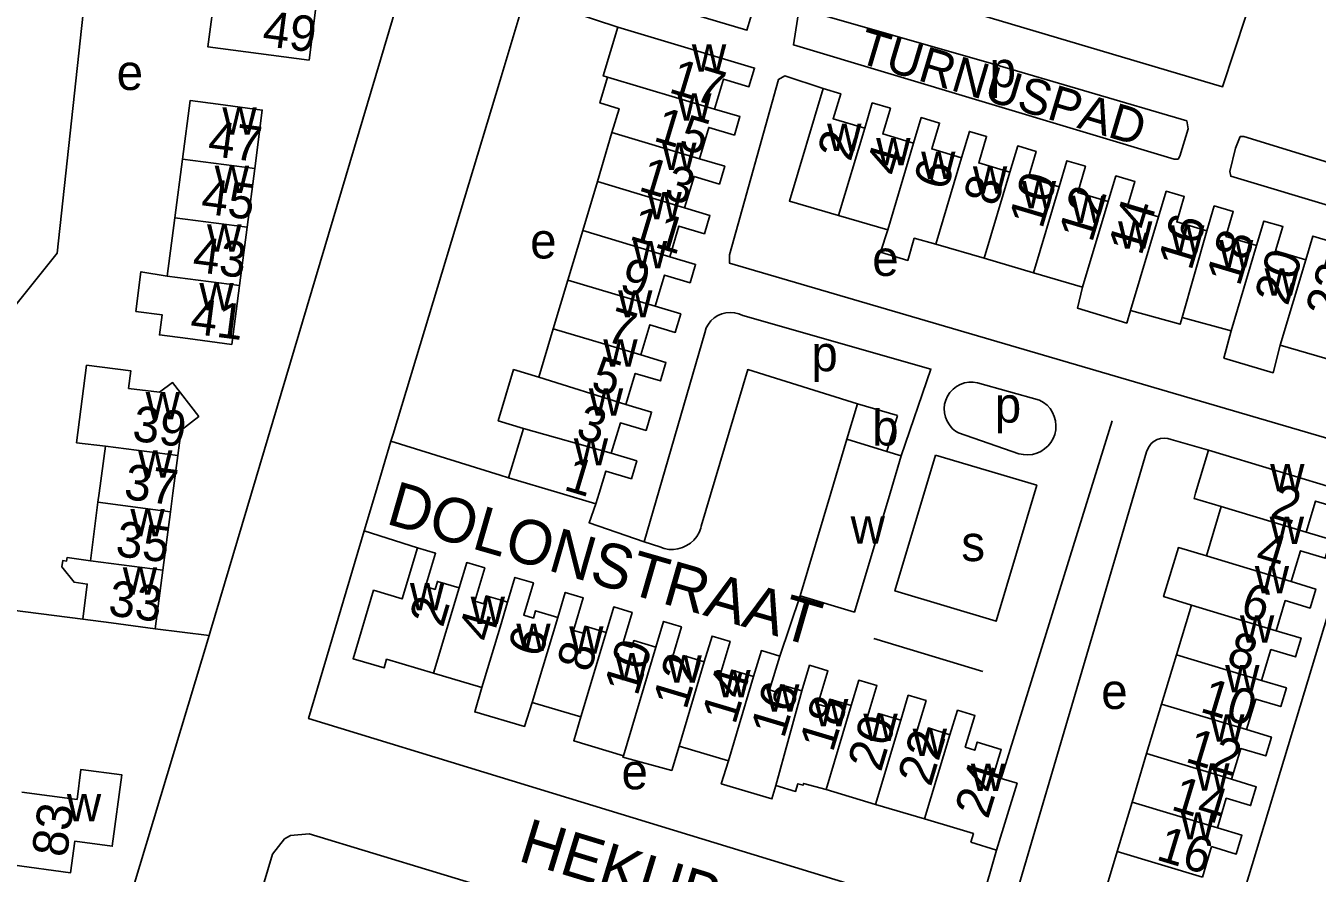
# Model space of a CAD drawing. Extents: x 161773 to 163836, y 384796 to 386521.
# Drawn here: x 162546.6 to 162692, y 386123.9 to 386219.3 of the extents above; entities that cross this region are included whole.
import ezdxf

# ---------------------------------------------------------------- set-up
doc = ezdxf.new("R2010")
doc.units = 0
for name, color, linetype in [('BLT_Basislijn', 7, 'Continuous'), ('BLT_Bebouwing', 7, 'Continuous'), ('BLT_Centroide', 7, 'Continuous'), ('BLT_Huisnummer', 7, 'Continuous'), ('BLT_Huisnummer_ tussenligend', 7, 'Continuous'), ('BLT_Onderverdeling_panden', 7, 'Continuous'), ('BLT_Straatnaam', 7, 'Continuous'), ('BLT_Straatnaam_verkleind', 7, 'Continuous')]:
    doc.layers.add(name, color=color, linetype=linetype)

msp = doc.modelspace()

# ---------------------------------------------------------------- linework, layer by layer
at = {"layer": 'BLT_Basislijn'}
for p, q in [((162613.25, 386219.12), (162602.84, 386222.55)), ((162623.03, 386184.72), (162616.23, 386161.19)), ((162653.73, 386179.08), (162660.73, 386177.13)), ((162668.89, 386174.8), (162656.4, 386134.57)), ((162658.4, 386171.11), (162651.6, 386173.44)), ((162675.53, 386172.72), (162679.74, 386171.49)), ((162672.77, 386171.3), (162656.86, 386117.36)), ((162590.71, 386160.52), (162584.72, 386162.44)), ((162616.23, 386161.19), (162617.98, 386160.61)), ((162531.15, 386155.33), (162553.03, 386152.48)), ((162633.77, 386155.11), (162631.48, 386148.33)), ((162561.18, 386151.41), (162567.26, 386150.66)), ((162654.32, 386146.61), (162642.07, 386150.31)), ((162655.88, 386126.5), (162653.53, 386118.37))]:
    msp.add_line(p, q, dxfattribs=at)
for points in [[(162567.26, 386150.66), (162567.41, 386151.18), (162572.02, 386166.67), (162600, 386260.71), (162602, 386267.43)], [(162540.64, 386154.24), (162544.92, 386187.1), (162550.17, 386193.67), (162555.68, 386244.61)], [(162606.67, 386234.6), (162681.32, 386212.4), (162683.95, 386220.36)], [(162603.89, 386225.89), (162627.79, 386218.76), (162629.02, 386222.85), (162605.25, 386230.19)], [(162602.84, 386222.55), (162600, 386213.16), (162587.96, 386173.29), (162587.72, 386172.5)], [(162655.32, 386215.01), (162633.68, 386221.2), (162633.02, 386217.11), (162675.87, 386204.25), (162676.31, 386204.27), (162676.5, 386204.6), (162677.44, 386207.67), (162677.29, 386208.56), (162655.32, 386215.01)], [(162636.36, 386212.21), (162632.07, 386213.62), (162631.35, 386213.24), (162625.82, 386193.5), (162625.83, 386192.55), (162698.69, 386171.22)], [(162708.24, 386199.25), (162683.7, 386206.8), (162683.3, 386206.8), (162682.79, 386205.5), (162682.15, 386202.86), (162682.23, 386202.34), (162706.87, 386194.97)], [(162627.31, 386186.66), (162626.86, 386186.85), (162626.39, 386186.97), (162625.91, 386187.01), (162625.43, 386186.97), (162624.95, 386186.85), (162624.51, 386186.66), (162624.1, 386186.39), (162623.74, 386186.07), (162623.45, 386185.68), (162623.21, 386185.26), (162623.03, 386184.72)], [(162627.31, 386186.66), (162648.49, 386180.63), (162645.14, 386170.87)], [(162622.64, 386162.94), (162627.87, 386180.58), (162640.23, 386176.73)], [(162653.73, 386179.08), (162653.24, 386179.15), (162652.75, 386179.15), (162652.27, 386179.07), (162651.8, 386178.9), (162651.37, 386178.67), (162650.98, 386178.37), (162650.64, 386178.01), (162650.37, 386177.6), (162650.17, 386177.15), (162650.04, 386176.68), (162649.99, 386176.18), (162650.02, 386175.69), (162650.12, 386175.21), (162650.31, 386174.76), (162650.57, 386174.34), (162650.89, 386173.96), (162651.27, 386173.65), (162651.6, 386173.44)], [(162660.73, 386177.13), (162661.17, 386176.88), (162661.56, 386176.56), (162661.9, 386176.18), (162662.18, 386175.75), (162662.38, 386175.29), (162662.52, 386174.8), (162662.57, 386174.29), (162662.54, 386173.78), (162662.43, 386173.28), (162662.25, 386172.81), (162661.99, 386172.37), (162661.67, 386171.98), (162661.29, 386171.64), (162660.87, 386171.36), (162660.4, 386171.15), (162659.91, 386171.02), (162659.4, 386170.97), (162658.9, 386171), (162658.4, 386171.11)], [(162587.72, 386172.5), (162585.98, 386166.67), (162584.72, 386162.44)], [(162600.96, 386168.4), (162600, 386168.7), (162587.72, 386172.5)], [(162675.53, 386172.72), (162675.14, 386172.83), (162674.74, 386172.87), (162674.34, 386172.82), (162673.96, 386172.7), (162673.6, 386172.51), (162673.29, 386172.24), (162673.04, 386171.93), (162672.86, 386171.57), (162672.77, 386171.3)], [(162649.02, 386170.96), (162644.44, 386155.67), (162655.83, 386152.26), (162660.4, 386167.56), (162649.02, 386170.96)], [(162610.78, 386165.46), (162610.02, 386163.33), (162616.23, 386161.19)], [(162697.19, 386166.25), (162681.58, 386114.67), (162679.99, 386111.76), (162677.03, 386111.25), (162656.86, 386117.36)], [(162584.72, 386162.44), (162578.45, 386141.3), (162600, 386134.72), (162649.94, 386119.45), (162650.62, 386119.25)], [(162617.98, 386160.61), (162618.47, 386160.44), (162618.99, 386160.34), (162619.51, 386160.33), (162620.02, 386160.39), (162620.52, 386160.54), (162620.99, 386160.76), (162621.43, 386161.04), (162621.81, 386161.39), (162622.14, 386161.8), (162622.4, 386162.25), (162622.59, 386162.74), (162622.64, 386162.94)], [(162517.27, 386157.06), (162513.65, 386127.2), (162515.18, 386125.55), (162517.05, 386125.1), (162553.21, 386120.54), (162557.19, 386120.68), (162558.62, 386122.04), (162567.26, 386150.66)], [(162600.83, 386121.55), (162600, 386121.81), (162578.52, 386128.33), (162576.4, 386128.15), (162575.75, 386127.77), (162574.38, 386126.02), (162560.06, 386077.9), (162560.16, 386075.81), (162561.56, 386074.11), (162571.68, 386071.14)]]:
    msp.add_lwpolyline(points, dxfattribs=at)
at = {"layer": 'BLT_Bebouwing'}
for p, q in [((162610.95, 386201.73), (162612.6, 386207.26)), ((162564.25, 386204.25), (162563.39, 386197.66)), ((162571.53, 386196.61), (162572.39, 386203.2)), ((162609.3, 386196.22), (162610.95, 386201.73)), ((162563.39, 386197.66), (162562.53, 386191.07)), ((162643.63, 386196.29), (162638.11, 386197.91)), ((162570.67, 386190.02), (162571.53, 386196.61)), ((162607.63, 386190.65), (162609.3, 386196.22)), ((162654.49, 386193.1), (162649.05, 386194.7)), ((162660.03, 386191.48), (162654.49, 386193.1)), ((162665.57, 386189.85), (162660.03, 386191.48)), ((162605.98, 386185.17), (162607.63, 386190.65)), ((162682.27, 386184.95), (162676.76, 386186.42)), ((162604.36, 386179.73), (162605.98, 386185.17)), ((162640.23, 386176.73), (162639.04, 386172.73)), ((162644.73, 386175.39), (162640.23, 386176.73)), ((162643.52, 386171.36), (162644.73, 386175.39)), ((162600.96, 386168.4), (162602.63, 386173.96)), ((162645.14, 386170.87), (162643.52, 386171.36)), ((162695.13, 386166.85), (162679.74, 386171.49)), ((162554.75, 386165.64), (162553.89, 386159.06)), ((162681.16, 386165.16), (162679.49, 386159.6)), ((162562.04, 386157.99), (162562.9, 386164.57)), ((162561.18, 386151.41), (162562.04, 386157.99)), ((162676.14, 386148.48), (162677.82, 386154.07)), ((162676.14, 386148.48), (162674.46, 386142.93)), ((162597.96, 386144.79), (162592.52, 386146.41)), ((162609.08, 386141.49), (162603.62, 386143.11)), ((162674.46, 386142.93), (162672.77, 386137.35)), ((162625.7, 386136.56), (162620.16, 386138.2)), ((162672.77, 386137.35), (162671.13, 386131.9)), ((162642.26, 386131.64), (162636.69, 386133.3)), ((162647.77, 386130), (162642.26, 386131.64)), ((162671.13, 386131.9), (162669.45, 386126.34)), ((162655.88, 386126.5), (162652.97, 386127.39)), ((162669.45, 386126.34), (162667.79, 386120.83))]:
    msp.add_line(p, q, dxfattribs=at)
for points in [[(162579.35, 386221.92), (162578.5, 386215.4), (162567.12, 386216.88), (162567.97, 386223.4), (162568.71, 386223.3)], [(162612.11, 386213.5), (162611.61, 386213.63), (162613.25, 386219.12)], [(162613.25, 386219.12), (162628.64, 386214.51), (162628.01, 386212.41), (162625.16, 386213.27), (162624.15, 386209.89)], [(162612.6, 386207.26), (162613.4, 386209.93), (162611.24, 386210.58), (162612.11, 386213.5)], [(162638.11, 386197.91), (162632.57, 386199.53), (162636.36, 386212.21)], [(162636.36, 386212.21), (162638.34, 386211.62), (162637.49, 386208.8), (162641.04, 386207.74)], [(162572.39, 386203.2), (162573.24, 386209.78), (162568.29, 386210.43), (162565.11, 386210.85), (162564.25, 386204.25)], [(162641.04, 386207.74), (162641.89, 386210.58), (162643.93, 386209.98), (162643.07, 386207.1), (162646.55, 386206.06)], [(162624.15, 386209.89), (162627, 386209.04), (162626.38, 386206.96), (162623.48, 386207.83), (162622.43, 386204.31)], [(162646.55, 386206.06), (162647.4, 386208.93), (162649.46, 386208.31), (162648.59, 386205.41), (162651.95, 386204.42)], [(162651.95, 386204.42), (162652.83, 386207.38), (162654.76, 386206.81), (162653.88, 386203.84), (162657.39, 386202.8)], [(162657.39, 386202.8), (162658.26, 386205.74), (162660.33, 386205.12), (162659.46, 386202.19), (162662.93, 386201.16)], [(162622.43, 386204.31), (162625.29, 386203.46), (162624.69, 386201.46), (162621.83, 386202.31), (162620.77, 386198.78)], [(162662.93, 386201.16), (162663.79, 386204.08), (162665.89, 386203.46), (162665.02, 386200.51), (162668.45, 386199.49)], [(162668.45, 386199.49), (162669.31, 386202.38), (162671.46, 386201.75), (162670.59, 386198.8), (162674.12, 386197.76)], [(162674.12, 386197.76), (162674.98, 386200.65), (162677.01, 386200.05), (162676.16, 386197.19), (162679.54, 386196.18)], [(162620.77, 386198.78), (162623.62, 386197.93), (162623.01, 386195.87), (162620.14, 386196.73), (162619.11, 386193.28)], [(162679.54, 386196.18), (162680.38, 386199), (162682.52, 386198.36), (162681.69, 386195.57), (162685.14, 386194.55)], [(162685.14, 386194.55), (162685.96, 386197.29), (162688.1, 386196.66), (162687.29, 386193.94), (162690.67, 386192.93)], [(162649.05, 386194.7), (162646.61, 386195.36), (162645.88, 386192.86), (162642.83, 386193.78), (162643.63, 386196.29)], [(162690.67, 386192.93), (162691.46, 386195.6), (162693.62, 386194.96), (162692.82, 386192.27), (162696.31, 386191.24)], [(162619.11, 386193.28), (162622.01, 386192.41), (162621.39, 386190.35), (162618.5, 386191.21), (162617.45, 386187.71)], [(162562.53, 386191.07), (162559.59, 386191.58), (162559.01, 386187.13), (162561.96, 386186.75), (162561.67, 386184.47), (162564.85, 386184.06), (162569.8, 386183.41), (162570.67, 386190.02)], [(162670.97, 386187.24), (162670.54, 386185.8), (162664.98, 386187.49), (162665.57, 386189.85)], [(162617.45, 386187.71), (162620.34, 386186.84), (162619.72, 386184.76), (162616.85, 386185.62), (162615.83, 386182.22)], [(162676.76, 386186.42), (162676.53, 386185.68), (162670.97, 386187.24)], [(162687.8, 386183.33), (162687.03, 386180.21), (162681.47, 386181.86), (162682.27, 386184.95)], [(162693.45, 386181.67), (162692.81, 386181.86), (162687.8, 386183.33)], [(162563.73, 386170.89), (162564.1, 386173.75), (162566.09, 386175.3), (162563.15, 386179.11), (162561.69, 386178.02), (162558.2, 386178.45), (162558.45, 386180.43), (162553.47, 386181.07), (162552.35, 386172.34), (162555.58, 386171.96)], [(162615.83, 386182.22), (162618.67, 386181.37), (162618.05, 386179.3), (162615.21, 386180.15), (162614.17, 386176.66)], [(162602.63, 386173.96), (162599.8, 386174.81), (162601.52, 386180.58), (162604.36, 386179.73)], [(162614.17, 386176.66), (162617.06, 386175.79), (162616.43, 386173.72), (162613.54, 386174.58), (162612.52, 386171.16)], [(162639.04, 386172.73), (162637.23, 386166.67), (162633.77, 386155.11)], [(162555.58, 386171.96), (162554.89, 386166.67), (162554.75, 386165.64)], [(162562.9, 386164.57), (162563.18, 386166.67), (162563.73, 386170.89)], [(162612.52, 386171.16), (162615.39, 386170.3), (162614.78, 386168.29), (162611.89, 386169.16), (162611.14, 386166.67), (162610.78, 386165.46)], [(162633.77, 386155.11), (162639.89, 386153.28), (162643.89, 386166.67), (162645.14, 386170.87)], [(162679.74, 386171.49), (162678.28, 386166.67), (162678.11, 386166.08), (162681.16, 386165.16)], [(162610.78, 386165.46), (162606.75, 386166.67), (162600.96, 386168.4)], [(162690.71, 386162.28), (162691.77, 386165.78), (162694.56, 386164.94), (162695.08, 386166.67), (162695.13, 386166.85)], [(162689.03, 386156.72), (162690.08, 386160.18), (162692.87, 386159.34), (162693.5, 386161.44), (162690.71, 386162.28)], [(162553.89, 386159.06), (162551.27, 386159.42), (162551.22, 386159.02), (162550.78, 386159.08), (162550.68, 386158.36), (162552.06, 386156.64), (162553.55, 386156.44), (162553.03, 386152.48)], [(162592.52, 386146.41), (162587.23, 386147.98), (162586.94, 386147), (162583.46, 386148.04), (162585.76, 386155.74), (162588.99, 386154.77), (162590.71, 386160.52)], [(162590.71, 386160.52), (162592.75, 386159.91), (162591.62, 386156.16), (162592.69, 386155.84), (162592.96, 386156.74), (162595.4, 386156.01)], [(162679.49, 386159.6), (162676.34, 386160.54), (162674.68, 386155.03), (162677.82, 386154.07)], [(162595.4, 386156.01), (162596.25, 386158.86), (162598.27, 386158.26), (162597.15, 386154.52), (162598.18, 386154.21), (162598.45, 386155.11), (162600, 386154.65), (162600.84, 386154.4)], [(162600.84, 386154.4), (162601.67, 386157.19), (162603.76, 386156.57), (162602.67, 386152.93), (162603.75, 386152.6), (162603.99, 386153.43), (162606.49, 386152.69)], [(162687.35, 386151.19), (162688.37, 386154.57), (162691.16, 386153.73), (162691.81, 386155.88), (162689.03, 386156.72)], [(162606.49, 386152.69), (162607.33, 386155.5), (162609.37, 386154.89), (162608.27, 386151.22), (162609.34, 386150.9), (162609.57, 386151.69), (162611.93, 386150.99)], [(162611.93, 386150.99), (162612.79, 386153.87), (162614.86, 386153.25), (162613.77, 386149.59), (162614.83, 386149.28), (162615.06, 386150.07), (162617.54, 386149.33)], [(162553.03, 386152.48), (162556.23, 386152.06), (162561.18, 386151.41)], [(162617.54, 386149.33), (162618.41, 386152.23), (162620.42, 386151.62), (162619.32, 386147.94), (162620.42, 386147.61), (162620.65, 386148.38), (162622.99, 386147.68)], [(162622.99, 386147.68), (162623.86, 386150.58), (162625.89, 386149.98), (162624.76, 386146.22), (162625.84, 386145.9), (162626.09, 386146.75), (162628.53, 386146.02)], [(162685.71, 386145.59), (162686.76, 386149.06), (162689.51, 386148.23), (162690.16, 386150.35), (162687.35, 386151.19)], [(162628.53, 386146.02), (162629.41, 386148.95), (162631.48, 386148.33)], [(162631.48, 386148.33), (162630.34, 386144.52), (162631.36, 386144.21), (162631.63, 386145.11), (162633.97, 386144.41)], [(162633.97, 386144.41), (162634.83, 386147.29), (162636.9, 386146.67), (162635.77, 386142.91), (162636.85, 386142.59), (162637.11, 386143.48), (162639.52, 386142.76)], [(162603.62, 386143.11), (162602.76, 386140.41), (162597.16, 386142.05), (162597.96, 386144.79)], [(162639.52, 386142.76), (162640.38, 386145.62), (162642.41, 386145.01), (162641.29, 386141.26), (162642.31, 386140.96), (162642.58, 386141.86), (162645.1, 386141.11)], [(162684.02, 386140.05), (162685.05, 386143.49), (162687.87, 386142.64), (162688.5, 386144.75), (162685.71, 386145.59)], [(162645.1, 386141.11), (162645.94, 386143.93), (162647.95, 386143.33), (162646.84, 386139.62), (162647.93, 386139.29), (162648.21, 386140.24), (162650.61, 386139.48)], [(162650.61, 386139.48), (162651.49, 386142.24), (162653.44, 386141.64), (162652.35, 386138.08), (162653.43, 386137.74), (162653.71, 386138.66), (162656.41, 386137.83), (162655.49, 386134.84), (162656.4, 386134.57)], [(162613.89, 386137.11), (162608.3, 386138.8), (162609.08, 386141.49)], [(162682.34, 386134.46), (162683.39, 386137.94), (162686.17, 386137.1), (162686.81, 386139.21), (162684.02, 386140.05)], [(162620.16, 386138.2), (162619.33, 386135.47), (162613.83, 386136.94), (162613.89, 386137.11)], [(162631.05, 386133.76), (162630.6, 386132.26), (162624.89, 386133.97), (162625.7, 386136.56)], [(162545.11, 386124.82), (162551.67, 386123.95), (162552.14, 386127.49), (162556.35, 386126.93), (162557.42, 386134.97), (162552.83, 386135.57), (162552.39, 386132.2), (162546.19, 386133.02)], [(162656.4, 386134.57), (162658.19, 386134.02), (162655.88, 386126.5)], [(162680.73, 386129), (162681.73, 386132.34), (162684.47, 386131.51), (162685.11, 386133.63), (162682.34, 386134.46)], [(162636.69, 386133.3), (162634.16, 386134), (162634.1, 386133.79), (162633.52, 386133.96), (162633.26, 386133.1), (162631.05, 386133.76)], [(162652.97, 386127.39), (162653.27, 386128.35), (162651.42, 386128.92), (162647.77, 386130)], [(162679.04, 386123.45), (162680.08, 386126.89), (162682.86, 386126.05), (162683.5, 386128.17), (162680.73, 386129)]]:
    msp.add_lwpolyline(points, dxfattribs=at)
at = {"layer": 'BLT_Onderverdeling_panden'}
for p, q in [((162624.15, 386209.89), (162612.11, 386213.5)), ((162622.43, 386204.31), (162612.6, 386207.26)), ((162641.04, 386207.74), (162638.11, 386197.91)), ((162646.55, 386206.06), (162643.63, 386196.29)), ((162564.25, 386204.25), (162572.39, 386203.2)), ((162651.95, 386204.42), (162649.05, 386194.7)), ((162657.39, 386202.8), (162654.49, 386193.1)), ((162620.77, 386198.78), (162610.95, 386201.73)), ((162662.93, 386201.16), (162660.03, 386191.48)), ((162668.45, 386199.49), (162665.57, 386189.85)), ((162563.39, 386197.66), (162571.53, 386196.61)), ((162674.12, 386197.76), (162670.97, 386187.24)), ((162619.11, 386193.28), (162609.3, 386196.22)), ((162679.54, 386196.18), (162676.76, 386186.42)), ((162685.14, 386194.55), (162682.27, 386184.95)), ((162690.67, 386192.93), (162687.8, 386183.33)), ((162562.53, 386191.07), (162570.67, 386190.02)), ((162617.45, 386187.71), (162607.63, 386190.65)), ((162615.83, 386182.22), (162605.98, 386185.17)), ((162614.17, 386176.66), (162604.36, 386179.73)), ((162612.52, 386171.16), (162602.63, 386173.96)), ((162643.52, 386171.36), (162639.04, 386172.73)), ((162555.58, 386171.96), (162563.73, 386170.89)), ((162554.75, 386165.64), (162562.9, 386164.57)), ((162690.71, 386162.28), (162681.16, 386165.16)), ((162689.03, 386156.72), (162679.49, 386159.6)), ((162553.89, 386159.06), (162562.04, 386157.99)), ((162595.4, 386156.01), (162592.52, 386146.41)), ((162687.35, 386151.19), (162677.82, 386154.07)), ((162606.49, 386152.69), (162603.62, 386143.11)), ((162611.93, 386150.99), (162609.08, 386141.49)), ((162617.54, 386149.33), (162613.89, 386137.11)), ((162622.99, 386147.68), (162620.16, 386138.2)), ((162685.71, 386145.59), (162676.14, 386148.48)), ((162628.53, 386146.02), (162625.7, 386136.56)), ((162633.97, 386144.41), (162631.05, 386133.76)), ((162639.52, 386142.76), (162636.69, 386133.3)), ((162684.02, 386140.05), (162674.46, 386142.93)), ((162645.1, 386141.11), (162642.26, 386131.64)), ((162650.61, 386139.48), (162647.77, 386130)), ((162682.34, 386134.46), (162672.77, 386137.35)), ((162680.73, 386129), (162671.13, 386131.9)), ((162679.04, 386123.45), (162669.45, 386126.34))]:
    msp.add_line(p, q, dxfattribs=at)
msp.add_lwpolyline([(162600.84, 386154.4), (162600, 386151.6), (162597.96, 386144.79)], dxfattribs=at)

# ---------------------------------------------------------------- texts
at = {"layer": 'BLT_Centroide'}
for s, p in [('w', (162621.59, 386214.09)), ('e', (162556.85, 386212.04)), ('p', (162655.09, 386212.36)), ('w', (162619.93, 386208.59)), ('w', (162568.75, 386207.03)), ('w', (162636.81, 386205.17)), ('w', (162618.24, 386203.03)), ('w', (162642.33, 386203.56)), ('w', (162647.39, 386202.03)), ('w', (162567.89, 386200.44)), ('w', (162653.22, 386200.38)), ('w', (162658.72, 386198.73)), ('w', (162616.59, 386197.5)), ('w', (162664.25, 386197.09)), ('w', (162567.03, 386193.84)), ('w', (162669.55, 386194.2)), ('e', (162603.39, 386193.08)), ('w', (162675.41, 386193.75)), ('w', (162614.95, 386191.97)), ('e', (162641.89, 386191.12)), ('w', (162680.91, 386192.09)), ('w', (162686.06, 386188.88)), ('w', (162566.16, 386187.25)), ('w', (162613.29, 386186.44)), ('w', (162611.62, 386180.91)), ('p', (162635.04, 386180.39)), ('w', (162560.12, 386174.97)), ('w', (162609.99, 386175.38)), ('p', (162655.68, 386174.61)), ('b', (162641.88, 386172.03)), ('w', (162608.3, 386169.78)), ('w', (162559.26, 386168.41)), ('w', (162686.67, 386166.88)), ('w', (162558.4, 386161.81)), ('w', (162639.45, 386161)), ('w', (162686.62, 386160.94)), ('s', (162651.91, 386159.02)), ('w', (162557.54, 386155.25)), ('w', (162684.94, 386155.41)), ('w', (162589.86, 386153.47)), ('w', (162596.69, 386151.95)), ('w', (162601.83, 386148.92)), ('w', (162683.27, 386149.84)), ('w', (162607.78, 386148.62)), ('w', (162612.92, 386145.62)), ('w', (162618.84, 386145.34)), ('w', (162624.34, 386143.7)), ('w', (162681.61, 386144.25)), ('w', (162629.83, 386142.08)), ('e', (162667.66, 386142.38)), ('w', (162635.33, 386140.42)), ('w', (162640.89, 386138.77)), ('w', (162679.91, 386138.69)), ('w', (162646.44, 386137.09)), ('e', (162613.67, 386133.34)), ('w', (162652.98, 386133.16)), ('w', (162678.24, 386133.19)), ('w', (162551.25, 386129.75)), ('w', (162676.61, 386127.69))]:
    msp.add_text(s, height=4, dxfattribs=at).set_placement(p)
at = {"layer": 'BLT_Huisnummer'}
for s, rotation, p in [('49', 352.5818, (162573.14, 386217.03)), ('17', 343.3056, (162618.86, 386211.81)), ('47', 352.6344, (162567, 386204.66)), ('2', 73.3616, (162639.45, 386203.88)), ('13', 343.3104, (162615.46, 386200.76)), ('6', 73.3629, (162650.28, 386200.6)), ('10', 73.3632, (162661.02, 386196.31)), ('14', 73.3623, (162672.19, 386193.28)), ('18', 73.3616, (162683.24, 386189.84)), ('9', 343.3104, (162613.28, 386189.43)), ('41', 352.5637, (162565.01, 386184.66)), ('5', 343.3082, (162610.07, 386178.34)), ('39', 352.5542, (162558.5, 386172.59)), ('1', 343.3308, (162607.03, 386167.08)), ('2', 343.2133, (162686.52, 386163.99)), ('33', 352.5594, (162555.79, 386152.93)), ('6', 343.215, (162683.15, 386152.87)), ('2', 73.3446, (162593.55, 386151.44)), ('6', 73.3473, (162604.63, 386148.03)), ('10', 73.349, (162615.46, 386143.72)), ('14', 73.3485, (162626.46, 386140.51)), ('10', 343.2134, (162678.65, 386142.1)), ('18', 73.3446, (162637.45, 386137.39)), ('24', 72.938, (162654.91, 386129.88)), ('14', 343.2153, (162675.38, 386131.08)), ('83', 82.4745, (162551.24, 386125.59))]:
    msp.add_text(s, height=4, rotation=rotation, dxfattribs=at).set_placement(p)
at = {"layer": 'BLT_Huisnummer_ tussenligend'}
for s, rotation, p in [('15', 343.3104, (162617.13, 386206.37)), ('4', 73.3616, (162644.94, 386202.19)), ('45', 352.5637, (162566.23, 386198.18)), ('8', 73.3629, (162655.9, 386198.82)), ('12', 73.3632, (162666.63, 386194.77)), ('11', 343.3104, (162614.42, 386195.25)), ('16', 73.3623, (162677.8, 386191.6)), ('43', 352.5637, (162565.28, 386191.63)), ('20', 73.3616, (162688.65, 386187.64)), ('22', 73.3616, (162694.38, 386186.1)), ('7', 343.3082, (162611.73, 386183.83)), ('3', 343.3308, (162608.39, 386172.94)), ('37', 352.5594, (162557.56, 386166.04)), ('35', 352.5594, (162556.62, 386159.61)), ('4', 343.2133, (162684.83, 386158.61)), ('4', 73.3446, (162599.04, 386149.76)), ('8', 343.215, (162681.61, 386147.37)), ('8', 73.3473, (162610.13, 386146.36)), ('12', 73.349, (162620.96, 386142.18)), ('16', 73.3485, (162631.95, 386138.96)), ('20', 73.3446, (162642.86, 386135.19)), ('22', 73.3446, (162648.48, 386133.53)), ('12', 343.2134, (162676.99, 386136.47)), ('16', 343.2153, (162673.71, 386125.46))]:
    msp.add_text(s, height=4, rotation=rotation, dxfattribs=at).set_placement(p)
at = {"layer": 'BLT_Straatnaam'}
for s, rotation, p in [('DOLONSTRAAT', 343.9178, (162587.03, 386163.27)), ('HEKUBASTRAAT', 343.0451, (162601.89, 386125.34))]:
    msp.add_text(s, height=5, rotation=rotation, dxfattribs=at).set_placement(p)
at = {"layer": 'BLT_Straatnaam_verkleind'}
msp.add_text('TURNUSPAD', height=4, rotation=343.4205, dxfattribs=at).set_placement((162640.04, 386215.2))

doc.saveas('drawing.dxf')
